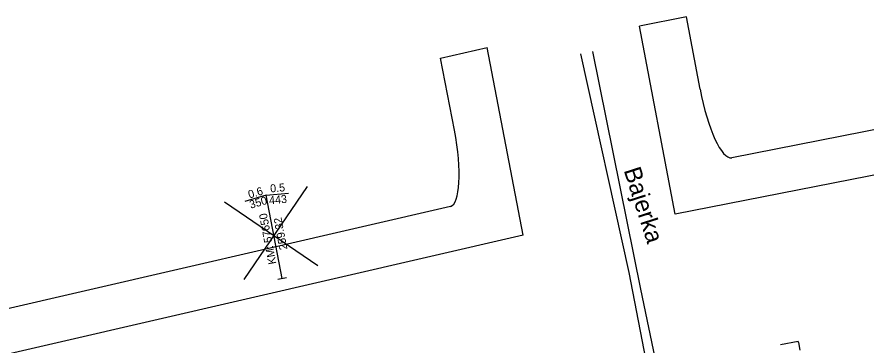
# Model space of a CAD drawing. Extents: x 6541740 to 6566395, y 5525066 to 5530361.
# Drawn here: x 6558111 to 6558206.4, y 5526366.5 to 5526403.3 of the extents above; entities that cross this region are included whole.
import ezdxf

# ---------------------------------------------------------------- set-up
doc = ezdxf.new("R2010")
doc.units = 0
for name, color, linetype in [('TOR_PRZEK_P-uklad odniesienia', 7, 'Continuous'), ('TOR_PS_ODW-osadniki', 7, 'Continuous'), ('TOR_PS_OPIS_T-symbole geometrii', 7, 'Continuous'), ('TOR_PS_T-wypelnienia', 7, 'Continuous'), ('TOR_W-warstwa dodatkowa 2', 7, 'Continuous')]:
    doc.layers.add(name, color=color, linetype=linetype)

msp = doc.modelspace()

# ---------------------------------------------------------------- linework, layer by layer
at = {"layer": 'TOR_PRZEK_P-uklad odniesienia'}
for p, q in [((6558136.509, 5526373.819), (6558143.635, 5526384.278)), ((6558136.509, 5526373.819), (6558143.635, 5526384.278)), ((6558144.764, 5526375.384), (6558134.305, 5526382.509)), ((6558144.764, 5526375.384), (6558134.305, 5526382.509))]:
    msp.add_line(p, q, dxfattribs=at)
at = {"layer": 'TOR_PS_ODW-osadniki'}
for p, q in [((6558138.984, 5526383.32), (6558136.574, 5526382.609)), ((6558138.984, 5526383.32), (6558136.574, 5526382.609)), ((6558138.984, 5526383.32), (6558141.487, 5526383.54)), ((6558138.984, 5526383.32), (6558141.487, 5526383.54)), ((6558140.758, 5526373.955), (6558138.984, 5526383.32)), ((6558140.758, 5526373.955), (6558138.984, 5526383.32)), ((6558140.267, 5526373.862), (6558141.249, 5526374.048)), ((6558140.267, 5526373.862), (6558141.249, 5526374.048))]:
    msp.add_line(p, q, dxfattribs=at)
at = {"layer": 'TOR_PS_OPIS_T-symbole geometrii'}
for p, q in [((6558186.216, 5526403.341), (6558180.941, 5526402.309)), ((6558186.216, 5526403.341), (6558180.941, 5526402.309)), ((6558187.756, 5526395.236), (6558186.216, 5526403.341)), ((6558187.756, 5526395.236), (6558186.216, 5526403.341)), ((6558184.953, 5526381.187), (6558180.941, 5526402.309)), ((6558184.953, 5526381.187), (6558180.941, 5526402.309)), ((6558158.58, 5526398.713), (6558163.821, 5526399.923)), ((6558158.58, 5526398.713), (6558163.821, 5526399.923)), ((6558167.877, 5526378.81), (6558163.821, 5526399.923)), ((6558167.877, 5526378.81), (6558163.821, 5526399.923)), ((6558252.65, 5526399.525), (6558191.319, 5526387.527)), ((6558252.65, 5526399.525), (6558191.319, 5526387.527)), ((6558160.136, 5526390.612), (6558158.58, 5526398.713)), ((6558160.136, 5526390.612), (6558158.58, 5526398.713)), ((6558253.583, 5526394.613), (6558184.953, 5526381.187)), ((6558253.583, 5526394.613), (6558184.953, 5526381.187)), ((6558159.682, 5526382.046), (6558093.712, 5526366.825)), ((6558159.682, 5526382.046), (6558093.712, 5526366.825))]:
    msp.add_line(p, q, dxfattribs=at)
msp.add_lwpolyline([(6558167.877, 5526378.81), (6558094.657, 5526361.916), (6558004.064, 5526338.849)], dxfattribs=at)
msp.add_lwpolyline([(6558167.877, 5526378.81), (6558094.657, 5526361.916), (6558004.064, 5526338.849)], dxfattribs=at)
for centre, start_param, end_param in [((6558189.78, 5526395.632), 4.713855, 6.284651), ((6558189.78, 5526395.632), 4.713855, 6.284651), ((6558158.125, 5526390.148), 0.009863, 1.580659), ((6558158.125, 5526390.148), 0.009863, 1.580659)]:
    msp.add_ellipse(centre, major_axis=(1.536, -8.106), ratio=0.25, start_param=start_param, end_param=end_param, dxfattribs=at)
at = {"layer": 'TOR_PS_T-wypelnienia'}
for points in [[(6558194.463, 5526302.241), (6558194.336, 5526303.569), (6558193.957, 5526306.102), (6558186.359, 5526340.675), (6558179.796, 5526374.614), (6558174.342, 5526399.206)], [(6558194.463, 5526302.241), (6558194.336, 5526303.569), (6558193.957, 5526306.102), (6558186.359, 5526340.675), (6558179.796, 5526374.614), (6558174.342, 5526399.206)], [(6558175.668, 5526399.457), (6558181.059, 5526372.762), (6558187.681, 5526340.99), (6558194.72, 5526309.384), (6558195.437, 5526302.302)], [(6558175.668, 5526399.457), (6558181.059, 5526372.762), (6558187.681, 5526340.99), (6558194.72, 5526309.384), (6558195.437, 5526302.302)]]:
    msp.add_lwpolyline(points, dxfattribs=at)
at = {"layer": 'TOR_W-warstwa dodatkowa 2'}
for p, q in [((6558198.789, 5526366.874), (6558196.787, 5526366.493)), ((6558198.789, 5526366.874), (6558196.787, 5526366.493)), ((6558198.813, 5526366.746), (6558198.789, 5526366.874)), ((6558198.813, 5526366.746), (6558198.789, 5526366.874))]:
    msp.add_line(p, q, dxfattribs=at)
msp.add_lwpolyline([(6558198.813, 5526366.746), (6558198.977, 5526365.879)], dxfattribs=at)
msp.add_lwpolyline([(6558198.813, 5526366.746), (6558198.977, 5526365.879)], dxfattribs=at)

# ---------------------------------------------------------------- texts
at = {"layer": 'TOR_PS_ODW-osadniki'}
for s, rotation, p in [('0.6', 16.43657, (6558137.092, 5526382.934)), ('0.6', 16.43657, (6558137.092, 5526382.934)), ('0.5', 5.01538, (6558139.46, 5526383.613)), ('0.5', 5.01538, (6558139.46, 5526383.613)), ('350', 16.43657, (6558137.24, 5526381.782)), ('350', 16.43657, (6558137.24, 5526381.782)), ('443', 5.01538, (6558139.337, 5526382.281)), ('443', 5.01538, (6558139.337, 5526382.281)), ('KM: 57650', 100.72597, (6558140.125, 5526375.622)), ('KM: 57650', 100.72597, (6558140.125, 5526375.622)), ('259.32', 100.72597, (6558141.368, 5526377.256)), ('259.32', 100.72597, (6558141.368, 5526377.256))]:
    msp.add_text(s, height=0.9, rotation=rotation, dxfattribs=at).set_placement(p)
at = {"layer": 'TOR_PS_T-wypelnienia'}
msp.add_text('Bajerka', height=1.9388, rotation=287.8237, dxfattribs=at).set_placement((6558179.157, 5526386.118))
msp.add_text('Bajerka', height=1.9388, rotation=287.8237, dxfattribs=at).set_placement((6558179.157, 5526386.118))

doc.saveas('drawing.dxf')
